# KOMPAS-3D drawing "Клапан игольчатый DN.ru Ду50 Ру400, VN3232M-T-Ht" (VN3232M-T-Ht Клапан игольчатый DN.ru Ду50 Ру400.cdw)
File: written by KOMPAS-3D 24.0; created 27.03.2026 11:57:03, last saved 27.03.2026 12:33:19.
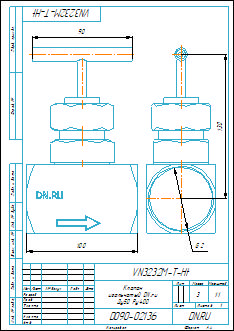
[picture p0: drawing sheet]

Document properties: Автор: Илья; Форматы листов документа: A4; Полное имя файла: VN3232M-T-Ht Клапан игольчатый DN.ru Ду50 Ру400.m3d; Масса: 3; Наименование: Клапан игольчатый DN.ru Ду50 Ру400; Количество листов документа: 1; Примечание: D090-02136

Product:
- Body: Body1  | qty 1
    Масса: 2.961611
- Part/product: Клапан игольчатый DN.ru Ду50 Ру400  | designation VN3232M-T-Ht
    Масса: 3
    Раздел спецификации: Прочие изделия
    Примечание: D090-02136

Views: Вид 1, Слева, Проекционный вид 2
Referenced files in D:\Обмен\Заказы с фриланса\DN.ru\VNxxM-T-Ht Клапан игольчатый DN.ru Ду8-50 Ру400\VN3232M-T-Ht Клапан игольчатый DN.ru Ду8-50 Ру400\DN8\: VN3232M-T-Ht Клапан игольчатый DN.ru Ду8 Ру400.m3d, VN3232M-T-Ht Клапан игольчатый DN.ru Ду8 Ру400.cdw
Referenced files in D:\Обмен\Заказы с фриланса\DN.ru\VNxxM-T-Ht Клапан игольчатый DN.ru Ду8-50 Ру400\VN3232M-T-Ht Клапан игольчатый DN.ru Ду8-50 Ру400\DN50\: VN3232M-T-Ht Клапан игольчатый DN.ru Ду50 Ру400.m3d
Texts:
  VN3232M-T-Ht
  Клапан
  игольчатый DN.ru
  Ду50 Ру400
  Body1
  Клапан игольчатый DN.ru Ду50 Ру400
  VN3232M-T-Ht Клапан игольчатый DN.ru Ду50 Ру400
Dimensions and other numbers on the sheet: 0; 3; 2; 4; 90; 100; 130; 1:1; 1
